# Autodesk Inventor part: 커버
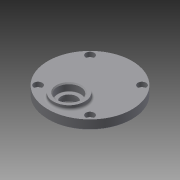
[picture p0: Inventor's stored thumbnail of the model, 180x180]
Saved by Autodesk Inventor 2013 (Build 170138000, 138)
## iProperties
Created: 2015-07
Part Number: 커버
Material: 일반
Document SubType Name: Modeling
Designer: user
Density: 1 g/cm^3
Author: user
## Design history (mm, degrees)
sketch "스케치1"
  geometry: C1 r 40 at (0, 0); 1 further point
  constraints: 1 centre point, 1 coincident
  dimensions: "d0" = 80 diameter of C1
extrude "돌출1" new body sketch "스케치1" distance "d1" = 9; taper "d2" = 0 deg
sketch "스케치2"
  geometry: L1 (0, 0)-(24.749, 24.749); L2 (0, 0)-(35, 0); L3 (0, 0)-(-24.749, 24.749); L4 (0, 0)-(24.749, -24.749); L5 (0, 0)-(-24.749, -24.749); C1 r 40 at (0, 0) reference; A1 r 35 centre (0, 0) between (24.749, 24.749) and (-24.749, 24.749); 4 further points
  constraints: 10 end point, 5 coincident, 4 point on circle, 2 perpendicular, 1 centre point, 1 collinear, 1 equal length, 1 horizontal
  dimensions: "d3" = 70 diameter of A1; "d4" = 45 deg angle of L2 L1
hole "구멍1" sketch "스케치2" at (24.749, 24.749), (-24.749, 24.749), (-24.749, -24.749), (24.749, -24.749) diameter "d5" = 4.5; stored, may be unused: countersink angle "d9" = 90 deg, drill point angle "d11" = 118 deg; dims "d6" = 6, "d7" = 8, "d8" = 4.4, "d10" = 30
sketch "스케치3"
  geometry: L1 (0, 0)-(0, -20); C1 r 40 at (0, 0) reference; C2 r 15 at (0, -20)
  constraints: 2 end point, 1 centre point, 1 coincident, 1 vertical
  dimensions: "d12" = 20 distance of L1.start L1.end; "d13" = 30 diameter of C2
extrude "돌출2" join sketch "스케치3" distance "d14" = 4; taper "d15" = 0 deg
sketch "스케치4"
  geometry: L1 (0, 0)-(0, -20); L2 (0, 0)-(0, 11); C1 r 40 at (0, 0) reference; C2 r 14 at (0, -20); C3 r 14 at (0, 11)
  constraints: 4 end point, 2 centre point, 2 coincident, 1 collinear, 1 vertical
  dimensions: "d16" = 20 distance of L1.start L1.end; "d17" = 28 diameter of C2; "d18" = 11 distance of L1.start L2.end; "d19" = 28 diameter of C3
extrude "돌출3" join sketch "스케치4" distance "d20" = 3; taper "d21" = 0 deg
sketch "스케치5"
  geometry: C1 r 15 at (0, 0) reference; C2 r 11 at (0, 0); 1 further point
  constraints: 1 centre point, 1 coincident
  dimensions: "d22" = 22 diameter of C2
extrude "돌출4" cut sketch "스케치5" distance "d23" = 7; taper "d24" = 0 deg
sketch "스케치6"
  geometry: C1 r 11 at (0, 0) reference; C2 r 7.5 at (0, 0); 1 further point
  constraints: 1 centre point, 1 coincident
  dimensions: "d25" = 15 diameter of C2
extrude "돌출5" cut sketch "스케치6" distance "d26" = 2; taper "d27" = 0 deg
sketch "스케치7"
  geometry: C1 r 14 at (0, 0) reference; C2 r 11 at (0, 0); 1 further point
  constraints: 1 centre point, 1 coincident
  dimensions: "d28" = 22 diameter of C2
extrude "돌출6" cut sketch "스케치7" distance "d29" = 7; taper "d30" = 0 deg
sketch "스케치8"
  geometry: C1 r 14 at (0, 0) reference; C2 r 11 at (0, 0); 1 further point
  constraints: 1 centre point, 1 coincident
  dimensions: "d31" = 22 diameter of C2
extrude "돌출7" cut sketch "스케치8" distance "d32" = 7; taper "d33" = 0 deg
sketch "스케치9"
  geometry: C1 r 9 at (0, 0); 2 further points
  constraints: 1 centre point, 1 coincident, 1 vertical alignment
  dimensions: "d34" = 18 diameter of C1
extrude "돌출8" cut sketch "스케치9" distance "d35" = 1; taper "d36" = 0 deg
fillet "모깎기1" dims "d37" = 0.3
fillet "모깎기2" dims "d38" = 2
chamfer "모따기1" distance "d39" = 1; stored, may be unused: second distance "d40" = 2, angle "d41" = 45 deg
chamfer "모따기2" distance "d42" = 1; stored, may be unused: second distance "d43" = 2, angle "d44" = 45 deg
fillet "모깎기3" dims "d45" = 2
node "솔리드1"
